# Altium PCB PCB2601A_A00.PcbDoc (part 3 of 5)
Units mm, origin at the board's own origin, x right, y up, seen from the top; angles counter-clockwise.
Board outline 30.4 x 51 mm, 8 copper layers (Top Layer, Signal Layer 2, Signal Layer 3, Signal Layer 4, Signal Layer 5, Signal Layer 6, Signal Layer 7, Bottom Layer), stack 1.492 mm thick; 194 components, 130 nets, 5039 pads, 478 vias.
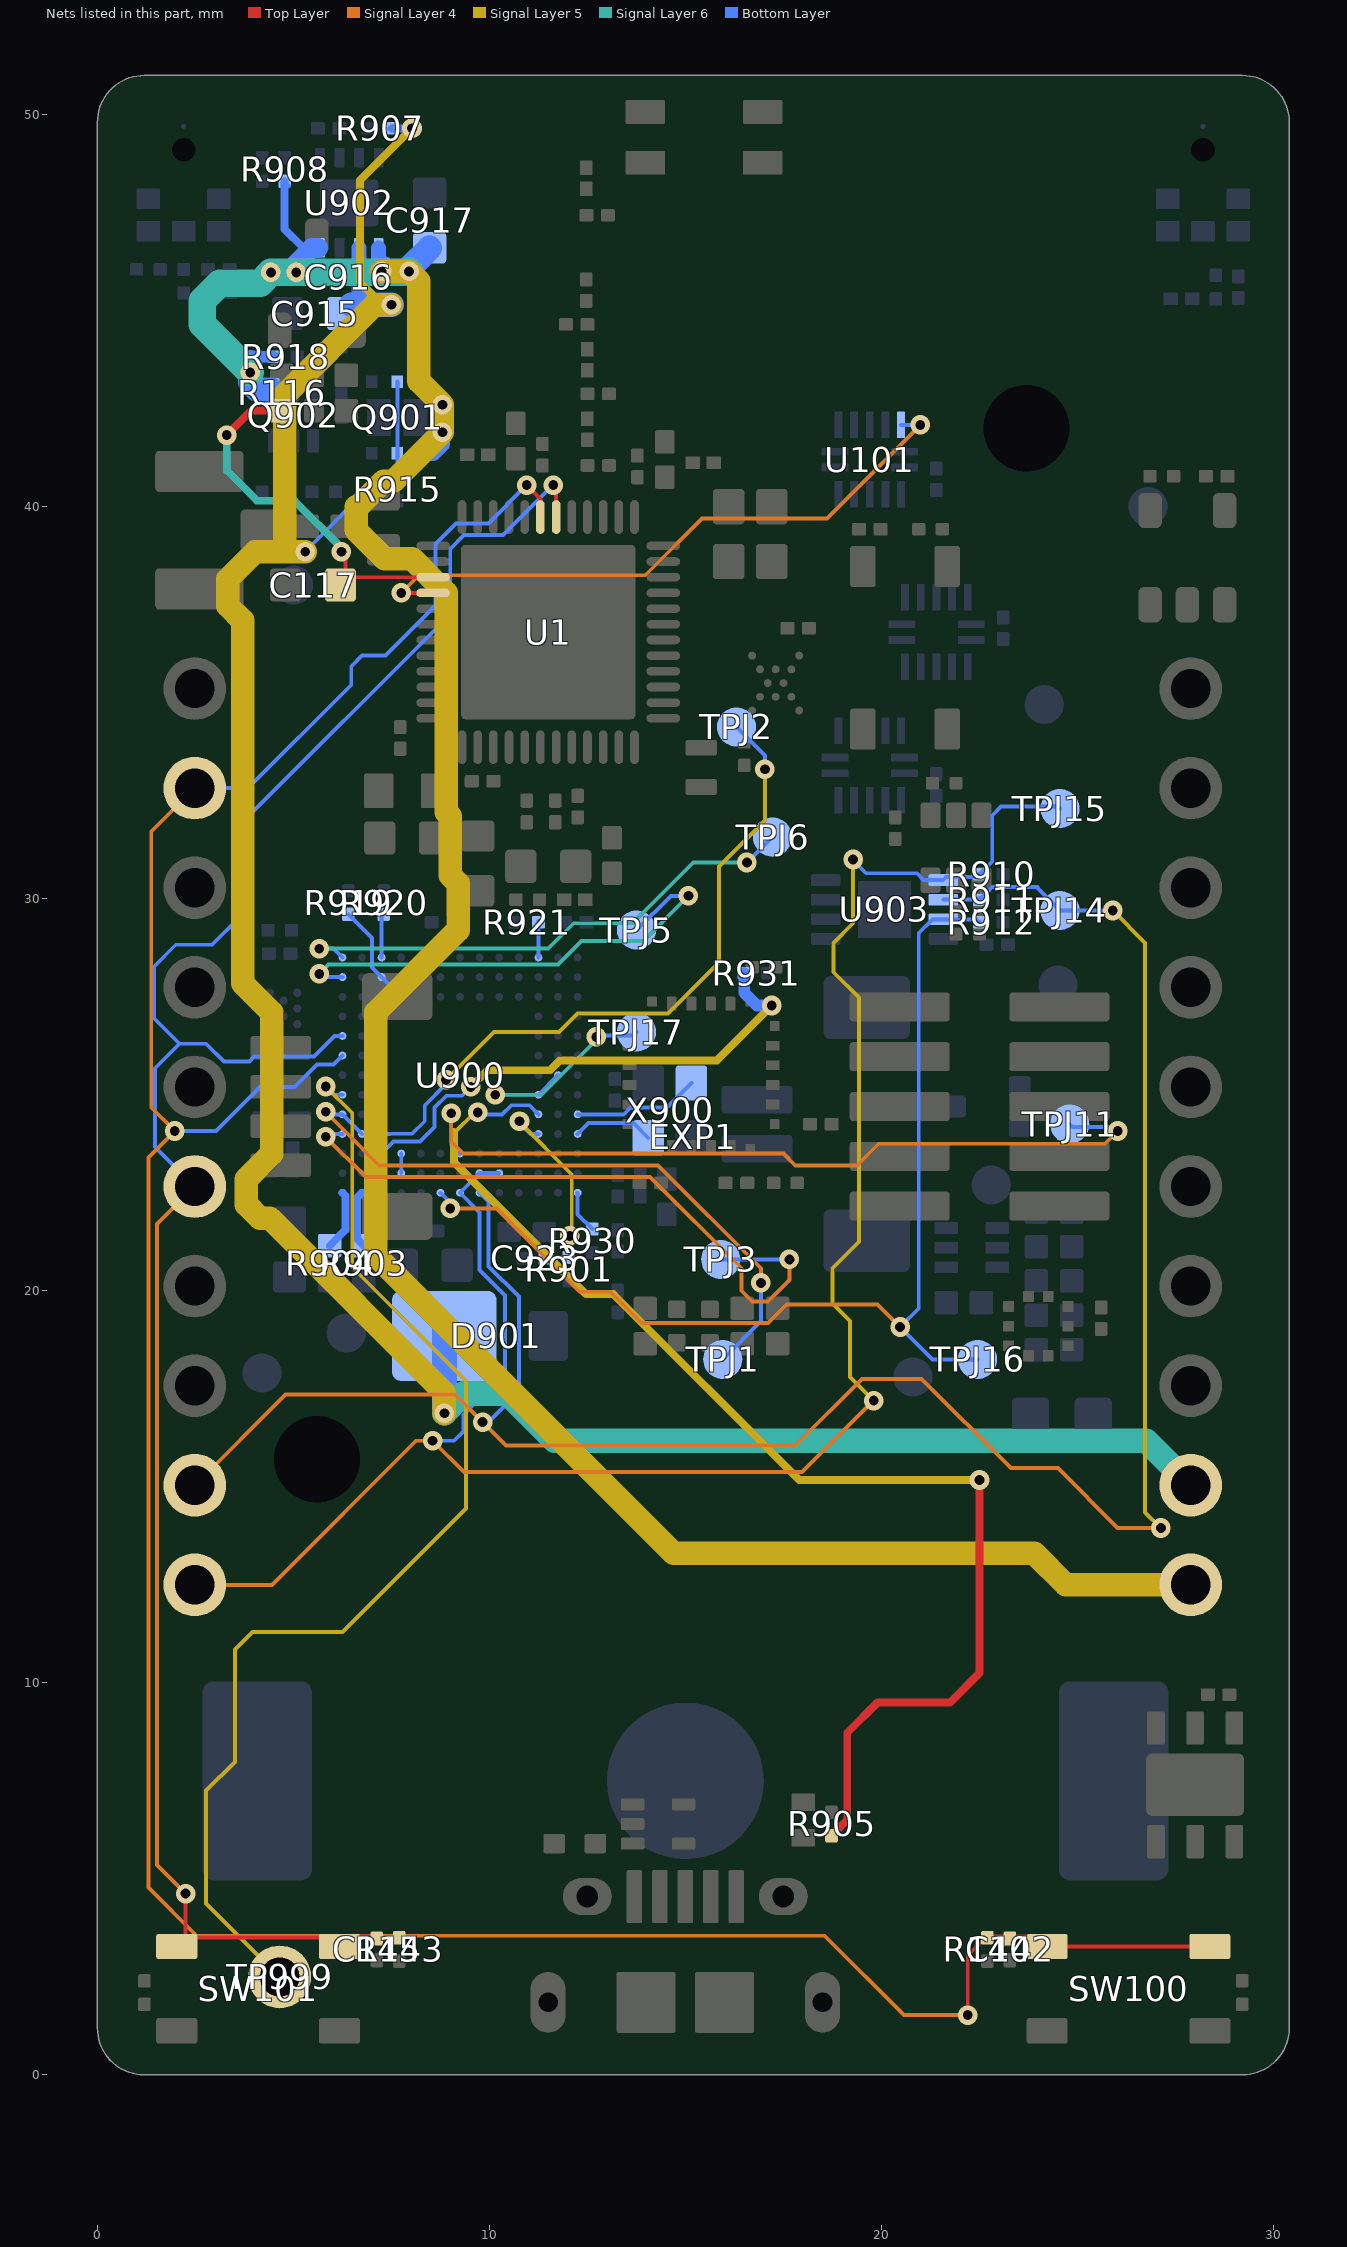
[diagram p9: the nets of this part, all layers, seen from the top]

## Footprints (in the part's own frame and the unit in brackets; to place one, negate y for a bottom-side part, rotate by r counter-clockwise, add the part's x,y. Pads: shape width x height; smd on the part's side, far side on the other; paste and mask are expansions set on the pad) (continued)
LOGO_SEGGER_8.0X4.0_SM [mil] "(210607)" (continued)
  round 0.8 on Mech2: 1(60.2,-56.26) 1(60.2,-56.26) 1(60.36,-56.74) 1(60.36,-56.74) 1(60.44,-56.9) 1(60.44,-56.9) 1(60.44,-56.82) 1(60.52,-29.06) 1(60.52,-29.06) 1(60.6,-57.14) 1(60.6,-57.14) 1(60.68,-57.3) 1(60.68,-57.3) 1(61.16,-36.58) 1(61.16,-36.58) 1(61.16,-29.46) 1(61.32,-57.94) 1(61.32,-57.94) 1(61.48,-29.7) 1(61.48,-29.7) 1(61.56,-58.02) 1(61.56,-58.02) 1(61.72,-58.1) 1(61.72,-58.1) 1(61.8,-36.42) 1(61.8,-36.42) 1(62.2,-58.26) 1(62.2,-58.26) 1(62.28,-40.98) 1(62.28,-40.98) 1(62.28,-36.1) 1(62.28,-36.1) 1(62.28,-30.5) 1(62.28,-30.5) 1(62.44,-58.26) 1(62.44,-58.26) 1(62.6,-35.94) 1(62.6,-35.94) 1(62.68,-58.34) 1(62.68,-58.34) 1(62.68,-35.86) 1(62.68,-30.82) 1(62.68,-30.82) 1(62.84,-41.06) 1(62.84,-41.06) 1(62.84,-31.06) 1(62.92,-58.34) 1(62.92,-58.34) 1(63.08,-35.46) 1(63.08,-35.46) 1(63.24,-58.26) 1(63.24,-58.26) 1(63.4,-34.98) 1(63.4,-34.98) 1(63.4,-32.02) 1(63.4,-32.02) 1(63.48,-34.74) 1(63.48,-34.74) 1(63.56,-58.26) 1(63.56,-58.26) 1(63.56,-32.34) 1(63.56,-32.34) 1(63.64,-41.22) 1(63.64,-41.22) 1(63.64,-34.42) 1(63.64,-34.42) 1(63.72,-34.26) 1(63.72,-34.18) 1(63.72,-34.18) 1(63.72,-32.74) 1(63.72,-32.74) 1(63.72,-32.66) 1(63.88,-58.18) 1(63.88,-58.18) 1(64.04,-41.38) 1(64.04,-41.38) 1(64.12,-58.18) 1(64.12,-58.18) 1(64.28,-41.46) 1(64.28,-41.46) 1(64.36,-58.02) 1(64.36,-58.02) 1(64.52,-57.94) 1(64.52,-57.94) 1(64.6,-41.62) 1(64.6,-41.62) 1(64.76,-57.78) 1(64.76,-57.78) 1(65,-42.02) 1(65,-42.02) 1(65.08,-57.46) 1(65.08,-57.46) 1(65.16,-57.3) 1(65.16,-57.3) 1(65.24,-42.34) 1(65.32,-57.06) 1(65.32,-57.06) 1(65.32,-42.5) 1(65.32,-42.5) 1(65.4,-56.82) 1(65.4,-56.74) 1(65.4,-56.74) 1(65.48,-56.5) 1(65.48,-56.5) 1(65.48,-56.18) 1(65.48,-56.18) 1(65.56,-55.94) 1(65.56,-55.94) 1(65.56,-55.14) 1(65.56,-53.54) 1(65.56,-51.94) 1(65.56,-50.34) 1(65.56,-48.74) 1(65.56,-47.14) 1(65.56,-45.54) 1(65.56,-43.94) 1(65.56,-43.46) 1(65.56,-43.46) 1(72.68,-54.02) 1(72.68,-54.02) 1(72.68,-52.66) 1(72.68,-51.06) 1(72.68,-49.46) 1(72.68,-47.86) 1(72.68,-46.26) 1(72.68,-44.66) 1(72.68,-43.06) 1(72.68,-41.46) 1(72.68,-39.86) 1(72.68,-38.18) 1(72.68,-36.58) 1(72.68,-34.98) 1(72.68,-33.38) 1(72.68,-31.78) 1(72.68,-30.5) 1(72.68,-30.5) 1(72.76,-54.58) 1(72.76,-54.58) 1(72.76,-54.26) 1(72.76,-30.18) 1(72.76,-29.94) 1(72.76,-29.94) 1(72.92,-55.3) 1(72.92,-55.3) 1(72.92,-55.06) 1(72.92,-55.06) 1(72.92,-29.38) 1(72.92,-29.38) 1(72.92,-29.14) 1(72.92,-29.14) 1(73,-55.54) 1(73,-55.54) 1(73,-28.98) 1(73,-28.98) 1(73.16,-55.78) 1(73.16,-55.78) 1(73.16,-28.74) 1(73.16,-28.74) 1(73.24,-55.94) 1(73.24,-28.58) 1(73.4,-56.26) 1(73.4,-56.26) 1(73.4,-28.26) 1(73.4,-28.26) 1(73.56,-56.42) 1(73.56,-56.42) 1(73.56,-28.1) 1(73.56,-28.1) 1(73.64,-56.58) 1(73.64,-56.58) 1(73.64,-27.94) 1(73.64,-27.94) 1(73.72,-56.66) 1(73.72,-56.66) 1(73.88,-56.74) 1(73.88,-56.74) 1(73.88,-27.7) 1(73.88,-27.7) 1(74.04,-56.9) 1(74.04,-56.9) 1(74.04,-27.62) 1(74.04,-27.62) 1(74.2,-27.46) 1(74.2,-27.46) 1(74.36,-57.06) 1(74.36,-57.06) 1(74.36,-27.46) 1(74.36,-27.46) 1(74.6,-57.14) 1(74.6,-57.14) 1(74.6,-27.3) 1(74.6,-27.3) 1(74.76,-57.22) 1(74.76,-57.22) 1(74.76,-27.22) 1(74.76,-27.22) 1(75,-57.3) 1(75,-57.3) 1(75,-27.22) 1(75,-27.22) 1(75.48,-27.06) 1(75.48,-27.06) 1(75.96,-57.46) 1(75.96,-57.46) 1(75.96,-26.98) 1(75.96,-26.98) 1(75.96,-26.98) 1(76.52,-57.54) 1(76.52,-57.54) 1(76.52,-26.98) 1(76.52,-26.98) 1(77.16,-26.9) 1(77.16,-26.9) 1(79.96,-51.94) 1(79.96,-51.94) 1(79.96,-51.06) 1(79.96,-49.46) 1(79.96,-47.86) 1(79.96,-46.26) 1(79.96,-44.66) 1(79.96,-44.02) 1(79.96,-44.02) 1(79.96,-38.74) 1(79.96,-38.74) 1(79.96,-38.18) 1(79.96,-36.58) 1(79.96,-34.98) 1(79.96,-33.38) 1(79.96,-32.26) 1(79.96,-32.26) 1(93.72,-38.74) 1(93.72,-38.74) 1(94.2,-44.02) 1(94.2,-44.02) 1(94.2,-38.82) 1(94.2,-38.82) 1(94.68,-43.94) 1(94.68,-43.94) 1(94.68,-38.82) 1(94.68,-38.82) 1(95.08,-43.94) 1(95.08,-43.94) 1(95.08,-38.9) 1(95.08,-38.9) 1(95.24,-26.9) 1(95.24,-26.9) 1(95.48,-43.86) 1(95.48,-43.86) 1(95.48,-38.9) 1(95.48,-38.9) 1(95.72,-32.26) 1(95.72,-32.26) 1(95.72,-26.98) 1(95.72,-26.98) 1(95.8,-43.78) 1(95.8,-43.78) 1(95.8,-39.06) 1(95.8,-39.06) 1(96.12,-43.62) 1(96.12,-43.62) 1(96.12,-39.14) 1(96.12,-39.14) 1(96.2,-32.18) 1(96.2,-32.18) 1(96.2,-26.98) 1(96.2,-26.98) 1(96.28,-26.98) 1(96.44,-43.54) 1(96.44,-43.54) 1(96.44,-39.3) 1(96.44,-39.3) 1(96.6,-32.18) 1(96.6,-32.18) 1(96.68,-51.94) 1(96.68,-51.94) 1(96.92,-43.22) 1(96.92,-43.22) 1(97.08,-43.06) 1(97.08,-42.98) 1(97.08,-42.98) 1(97.16,-57.54) 1(97.16,-57.54) 1(97.16,-52.02) 1(97.16,-52.02) 1(97.16,-39.78) 1(97.16,-39.78) 1(97.24,-39.86) 1(97.4,-32.02) 1(97.4,-32.02) 1(97.4,-27.22) 1(97.4,-27.22) 1(97.48,-42.58) 1(97.48,-42.58) 1(97.48,-40.26) 1(97.48,-40.26) 1(97.56,-52.02) 1(97.56,-52.02) 1(97.56,-42.26) 1(97.56,-42.26) 1(97.56,-40.5) 1(97.56,-40.5) 1(97.64,-42.02) 1(97.64,-42.02) 1(97.72,-41.7) 1(97.72,-41.7) 1(97.72,-41.46) 1(97.72,-41.14) 1(97.72,-41.14) 1(97.72,-31.86) 1(97.72,-31.86) 1(97.72,-27.3) 1(97.72,-27.3) 1(97.96,-31.78) 1(98.04,-31.78) 1(98.04,-31.78) 1(98.04,-27.46) 1(98.04,-27.46) 1(98.28,-31.62) 1(98.28,-31.62) 1(98.36,-57.3) 1(98.36,-57.3) 1(98.36,-52.18) 1(98.36,-52.18) 1(98.52,-31.38) 1(98.52,-31.38) 1(98.52,-27.78) 1(98.52,-27.78) 1(98.68,-57.14) 1(98.68,-57.14) 1(98.76,-31.22) 1(98.76,-31.22) 1(98.76,-28.02) 1(98.76,-28.02) 1(98.92,-56.98) 1(98.92,-56.98) 1(98.92,-30.98) 1(98.92,-30.98) 1(98.92,-28.26) 1(98.92,-28.26) 1(99,-52.5) 1(99,-52.5) 1(99,-30.74) 1(99,-30.74) 1(99,-28.5) 1(99,-28.5) 1(99.08,-28.58) 1(99.16,-30.5) 1(99.16,-30.5) 1(99.16,-28.74) 1(99.16,-28.74) 1(99.24,-56.82) 1(99.24,-56.82) 1(99.24,-30.26) 1(99.24,-30.26) 1(99.24,-28.98) 1(99.24,-28.98) 1(99.32,-52.66) 1(99.32,-30.18) 1(99.32,-29.94) 1(99.32,-29.94) 1(99.32,-29.3) 1(99.32,-29.3) 1(99.48,-56.66) 1(99.48,-56.66) 1(99.48,-52.82) 1(99.48,-52.82) 1(99.64,-56.42) 1(99.64,-56.42) 1(99.72,-53.06) 1(99.72,-53.06) 1(99.88,-56.18) 1(99.88,-56.18) 1(99.88,-53.3) 1(99.88,-53.3) 1(99.96,-55.94) 1(99.96,-55.94) 1(99.96,-55.94) 1(100.12,-55.7) 1(100.12,-55.7) 1(100.12,-53.78) 1(100.12,-53.78) 1(100.2,-55.38) 1(100.2,-55.38) 1(100.2,-55.06) 1(100.2,-55.06) 1(100.2,-54.42) 1(100.2,-54.42) 1(100.2,-54.26) 1(100.2,-54.1) 1(100.2,-54.1) 1(100.28,-54.74) 1(100.28,-54.74) 1(105.4,-54.98) 1(105.4,-54.98) 1(105.4,-54.66) 1(105.4,-53.06) 1(105.4,-51.46) 1(105.4,-49.86) 1(105.4,-48.26) 1(105.4,-46.66) 1(105.4,-45.06) 1(105.4,-43.46) 1(105.4,-41.86) 1(105.4,-40.26) 1(105.4,-38.58) 1(105.4,-36.98) 1(105.4,-35.38) 1(105.4,-33.78) 1(105.4,-32.18) 1(105.4,-31.06) 1(105.4,-31.06) 1(105.48,-55.38) 1(105.48,-55.38) 1(105.48,-30.58) 1(105.64,-56.02) 1(105.64,-56.02) 1(105.64,-29.38) 1(105.64,-29.38) 1(105.72,-29.14) 1(105.72,-29.14) 1(105.8,-56.34) 1(105.8,-56.34) 1(105.8,-56.34) 1(105.8,-28.98) 1(105.8,-28.98) 1(105.8,-28.98) 1(105.88,-28.74) 1(105.88,-28.74) 1(106.04,-28.42) 1(106.04,-28.42) 1(106.12,-56.82) 1(106.12,-56.82) 1(106.2,-28.26) 1(106.2,-28.26) 1(106.36,-27.94) 1(106.36,-27.94) 1(106.52,-27.86) 1(106.52,-27.86) 1(106.6,-57.3) 1(106.6,-57.3) 1(106.68,-27.7) 1(106.68,-27.7) 1(106.84,-57.46) 1(106.84,-57.46) 1(106.84,-27.62) 1(106.84,-27.62) 1(107,-27.46) 1(107,-27.46) 1(107.16,-57.62) 1(107.16,-57.62) 1(107.16,-27.46) 1(107.16,-27.46) 1(107.24,-27.38) 1(107.32,-27.3) 1(107.32,-27.3) 1(107.48,-57.7) 1(107.48,-57.7) 1(107.56,-27.22) 1(107.56,-27.22) 1(107.8,-27.22) 1(107.8,-27.22) 1(108.2,-27.06) 1(108.2,-27.06) 1(108.68,-57.94) 1(108.68,-57.94) 1(108.76,-26.98) 1(108.76,-26.98) 1(109.32,-26.98) 1(109.32,-26.98) 1(109.56,-57.94) 1(109.56,-57.94) 1(109.96,-26.9) 1(109.96,-26.9) 1(110.04,-57.86) 1(110.04,-57.86) 1(110.44,-57.78) 1(110.44,-57.78) 1(111.08,-57.62) 1(111.08,-57.62) 1(111.4,-57.46) 1(111.4,-57.46) 1(111.64,-57.3) 1(111.64,-57.3) 1(111.96,-57.06) 1(111.96,-57.06) 1(112.12,-56.9) 1(112.12,-56.9) 1(112.36,-56.58) 1(112.36,-56.58) 1(112.44,-56.34) 1(112.44,-56.34) 1(112.44,-56.34) 1(112.6,-56.02) 1(112.6,-56.02) 1(112.76,-55.38) 1(112.76,-55.38) 1(112.84,-54.98) 1(112.84,-54.98) 1(112.84,-54.66) 1(112.84,-53.06) 1(112.84,-51.46) 1(112.84,-49.86) 1(112.84,-48.26) 1(112.84,-46.66) 1(112.84,-45.62) 1(112.84,-45.62) 1(112.84,-40.34) 1(112.84,-40.34) 1(112.84,-40.26) 1(112.84,-38.58) 1(112.84,-36.98) 1(112.84,-35.38) 1(112.84,-33.78) 1(112.84,-32.18) 1(112.84,-32.18) 1(112.84,-32.18) 1(120.68,-45.62) 1(120.68,-45.62) 1(121.4,-45.7) 1(121.4,-45.7) 1(121.88,-32.18) 1(121.88,-32.18) 1(122.04,-45.7) 1(122.04,-45.7) 1(122.2,-32.18) 1(122.28,-40.34) 1(122.28,-40.34) 1(122.52,-32.26) 1(122.52,-32.26) 1(122.92,-40.26) 1(122.92,-40.26) 1(122.92,-26.9) 1(122.92,-26.9) 1(123,-40.26) 1(123.16,-45.86) 1(123.16,-45.86) 1(123.16,-32.26) 1(123.16,-32.26) 1(123.56,-45.94) 1(123.56,-45.94) 1(123.64,-32.34) 1(123.64,-32.34) 1(123.64,-26.98) 1(123.64,-26.98) 1(124.04,-46.1) 1(124.04,-46.1) 1(124.04,-40.1) 1(124.04,-40.1) 1(124.2,-46.18) 1(124.2,-46.18) 1(124.2,-32.5) 1(124.2,-32.5) 1(124.36,-46.34) 1(124.36,-46.34) 1(124.36,-26.98) 1(124.36,-26.98) 1(124.6,-32.58) 1(124.6,-32.58) 1(124.68,-46.5) 1(124.68,-46.5) 1(124.92,-46.66) 1(125,-39.78) 1(125,-39.78) 1(125,-32.82) 1(125,-32.82) 1(125,-27.06) 1(125,-27.06) 1(125.08,-46.9) 1(125.08,-46.9) 1(125.16,-47.14) 1(125.16,-47.14) 1(125.16,-39.7) 1(125.16,-39.7) 1(125.24,-32.9) 1(125.24,-32.9) 1(125.32,-47.3) 1(125.32,-47.3) 1(125.4,-39.54) 1(125.4,-39.54) 1(125.4,-32.98) 1(125.4,-32.98) 1(125.48,-47.78) 1(125.48,-47.78) 1(125.56,-48.1) 1(125.56,-48.1) 1(125.64,-48.26) 1(125.64,-33.14) 1(125.64,-33.14) 1(125.64,-27.06) 1(125.64,-27.06) 1(125.72,-48.66) 1(125.72,-48.66) 1(125.72,-39.38) 1(125.72,-39.38) 1(125.8,-33.22) 1(125.8,-33.22) 1(125.88,-49.38) 1(125.88,-49.38) 1(125.96,-33.38) 1(125.96,-33.38) 1(126.04,-51.06) 1(126.04,-51.06) 1(126.04,-50.18) 1(126.04,-50.18) 1(126.04,-49.86) 1(126.04,-33.54) 1(126.04,-33.54) 1(126.12,-51.46) 1(126.2,-52.18) 1(126.2,-52.18) 1(126.2,-33.62) 1(126.2,-33.62) 1(126.28,-53.14) 1(126.28,-53.14) 1(126.28,-53.06) 1(126.36,-33.78) 1(126.36,-33.78) 1(126.44,-54.02) 1(126.44,-54.02) 1(126.44,-38.66) 1(126.44,-38.66) 1(126.44,-38.58) 1(126.44,-34.02) 1(126.44,-34.02) 1(126.44,-33.78) 1(126.6,-54.82) 1(126.6,-54.82) 1(126.6,-54.66) 1(126.6,-38.42) 1(126.6,-38.42) 1(126.6,-34.18) 1(126.6,-34.18) 1(126.76,-34.5) 1(126.76,-34.5) 1(126.84,-55.78) 1(126.84,-55.78) 1(126.84,-37.94) 1(126.84,-37.94) 1(126.84,-34.74) 1(126.84,-34.74) 1(126.92,-37.7) 1(126.92,-37.7) 1(126.92,-37.46) 1(126.92,-37.46) 1(126.92,-34.9) 1(126.92,-34.9) 1(126.92,-27.22) 1(126.92,-27.22) 1(127,-56.02) 1(127,-56.02) 1(127,-37.22) 1(127,-37.22) 1(127,-35.3) 1(127,-35.3) 1(127,-35.14) 1(127,-35.14) 1(127.08,-56.26) 1(127.08,-56.26) 1(127.08,-36.98) 1(127.08,-36.74) 1(127.08,-36.74) 1(127.08,-35.78) 1(127.08,-35.78) 1(127.08,-35.38) 1(127.16,-56.34) 1(127.24,-56.5) 1(127.24,-56.5) 1(127.32,-56.66) 1(127.32,-56.66) 1(127.48,-56.82) 1(127.48,-56.82) 1(127.48,-27.38) 1(127.48,-27.38) 1(127.56,-56.98) 1(127.56,-56.98) 1(127.56,-27.38) 1(127.72,-57.06) 1(127.72,-57.06) 1(127.88,-57.22) 1(127.88,-57.22) 1(128.04,-57.3) 1(128.04,-57.3) 1(128.04,-27.46) 1(128.04,-27.46) 1(128.2,-57.46) 1(128.2,-57.46) 1(128.36,-57.54) 1(128.36,-57.54) 1(128.6,-57.62) 1(128.6,-57.62) 1(128.6,-27.62) 1(128.6,-27.62) 1(128.76,-57.7) 1(128.76,-57.7) 1(129.16,-42.82) 1(129.16,-42.82) 1(129.56,-27.94) 1(129.56,-27.94) 1(129.64,-43.06) 1(129.64,-43.06) 1(130.04,-28.18) 1(130.04,-28.18) 1(130.12,-43.22) 1(130.12,-43.22) 1(130.12,-42.58) 1(130.12,-42.58) 1(130.2,-57.94) 1(130.2,-57.94) 1(130.36,-42.42) 1(130.36,-42.42) 1(130.52,-43.38) 1(130.52,-43.38) 1(130.52,-28.34) 1(130.52,-28.34) 1(130.68,-43.46) 1(130.68,-42.34) 1(130.68,-42.34) 1(131.32,-43.86) 1(131.32,-43.86) 1(131.32,-28.82) 1(131.32,-28.82) 1(131.4,-41.86) 1(131.4,-41.86) 1(131.4,-41.86) 1(131.56,-57.94) 1(131.56,-57.94) 1(131.56,-28.98) 1(131.64,-44.1) 1(131.64,-44.1) 1(131.64,-29.06) 1(131.64,-29.06) 1(131.72,-41.7) 1(131.72,-41.7) 1(131.96,-57.86) 1(131.96,-57.86) 1(131.96,-41.54) 1(131.96,-41.54) 1(132.04,-29.38) 1(132.04,-29.38) 1(132.28,-57.78) 1(132.28,-57.78) 1(132.36,-41.14) 1(132.36,-41.14) 1(132.36,-29.62) 1(132.36,-29.62) 1(132.52,-44.98) 1(132.52,-44.98) 1(132.6,-57.62) 1(132.6,-57.62) 1(132.6,-45.06) 1(132.6,-40.98) 1(132.6,-40.98) 1(132.6,-29.94) 1(132.6,-29.94) 1(132.68,-45.38) 1(132.68,-45.38) 1(132.92,-57.54) 1(132.92,-57.54) 1(132.92,-45.7) 1(132.92,-45.7) 1(132.92,-40.5) 1(132.92,-40.5) 1(132.92,-30.34) 1(132.92,-30.34) 1(133.08,-46.1) 1(133.08,-46.1) 1(133.16,-57.38) 1(133.16,-57.38) 1(133.16,-40.34) 1(133.16,-40.34) 1(133.16,-30.58) 1(133.24,-46.58) 1(133.24,-46.58) 1(133.24,-40.26) 1(133.32,-46.66) 1(133.32,-40.1) 1(133.32,-40.1) 1(133.4,-30.98) 1(133.4,-30.98) 1(133.48,-57.22) 1(133.48,-57.22) 1(133.48,-39.78) 1(133.48,-39.78) 1(133.56,-48.26) 1(133.64,-50.82) 1(133.64,-50.82) 1(133.64,-49.86) 1(133.64,-48.98) 1(133.64,-48.98) 1(133.64,-39.54) 1(133.64,-39.54) 1(133.64,-31.38) 1(133.64,-31.38) 1(133.72,-56.98) 1(133.72,-56.98) 1(133.72,-51.38) 1(133.72,-51.38) 1(133.72,-39.3) 1(133.72,-39.3) 1(133.8,-52.1) 1(133.8,-52.1) 1(133.8,-51.78) 1(133.8,-51.78) 1(133.8,-51.46) 1(133.88,-56.74) 1(133.88,-56.74) 1(133.88,-39.06) 1(133.88,-39.06) 1(133.96,-52.74) 1(133.96,-52.74) 1(133.96,-38.74) 1(133.96,-38.74) 1(133.96,-32.18) 1(133.96,-32.18) 1(133.96,-32.18) 1(134.04,-56.58) 1(134.04,-56.58) 1(134.04,-53.22) 1(134.04,-53.22) 1(134.04,-53.06) 1(134.04,-38.58) 1(134.04,-38.5) 1(134.04,-38.5) 1(134.12,-32.66) 1(134.12,-32.66) 1(134.2,-56.34) 1(134.2,-56.26) 1(134.2,-56.26) 1(134.2,-53.7) 1(134.2,-53.7) 1(134.2,-38.18) 1(134.2,-38.18) 1(134.2,-37.94) 1(134.2,-37.94) 1(134.2,-33.06) 1(134.2,-33.06) 1(134.28,-54.18) 1(134.28,-54.18) 1(134.36,-56.02) 1(134.36,-56.02) 1(134.36,-33.54) 1(134.36,-33.54) 1(134.44,-55.78) 1(134.44,-55.78) 1(134.44,-54.66) 1(134.44,-54.58) 1(134.44,-54.58) 1(134.44,-36.98) 1(134.44,-36.98) 1(134.44,-36.98) 1(134.44,-34.58) 1(134.44,-34.58) 1(134.44,-34.02) 1(134.44,-34.02) 1(134.44,-33.78) 1(134.52,-36.34) 1(134.52,-36.34) 1(134.52,-35.38) 1(134.52,-35.06) 1(134.52,-35.06) 1(135.4,-5.14) 1(135.4,-5.14) 1(135.4,14.54) 1(135.4,14.54) 1(135.8,-14.34) 1(135.8,-14.34) 1(135.8,-5.22) 1(135.8,-5.22) 1(135.8,5.34) 1(135.8,5.34) 1(135.8,14.46) 1(135.8,14.46) 1(136.2,-5.22) 1(136.2,-5.22) 1(136.2,14.46) 1(136.2,14.46) 1(137,-14.1) 1(137,-14.1) 1(137,-5.38) 1(137,-5.38) 1(137,5.58) 1(137,5.58) 1(137,14.3) 1(137,14.3) 1(137.16,-14.02) 1(137.64,-13.78) 1(137.64,-13.78) 1(137.64,-5.7) 1(137.64,-5.7) 1(137.64,13.98) 1(137.64,13.98) 1(137.8,-13.62) 1(137.8,-13.62) 1(137.8,-5.86) 1(137.8,-5.86) 1(137.8,5.98) 1(137.8,5.98) 1(137.96,-13.54) 1(137.96,-13.54) 1(137.96,-5.94) 1(137.96,-5.94) 1(137.96,13.66) 1(137.96,13.66) 1(138.04,-5.94) 1(138.12,13.58) 1(138.12,13.58) 1(138.28,-13.22) 1(138.28,-13.22) 1(138.28,-6.26) 1(138.28,-6.26) 1(138.28,6.46) 1(138.28,6.46) 1(138.28,13.42) 1(138.28,13.42) 1(138.36,-13.06) 1(138.36,-13.06) 1(138.36,-6.42) 1(138.36,-6.42) 1(138.36,6.62) 1(138.36,6.62) 1(138.36,13.18) 1(138.36,13.18) 1(138.36,13.42) 1(138.52,-12.82) 1(138.52,-12.82) 1(138.52,-6.66) 1(138.52,-6.66) 1(138.52,6.78) 1(138.52,6.78) 1(138.52,13.02) 1(138.52,13.02) 1(138.6,-12.66) 1(138.6,-12.66) 1(138.6,6.94) 1(138.68,-12.42) 1(138.76,-12.18) 1(138.76,-12.18) 1(138.76,-7.38) 1(138.76,-7.38) 1(138.76,7.5) 1(138.76,7.5) 1(138.76,12.3) 1(138.76,12.3) 1(138.92,-11.86) 1(138.92,-11.86) 1(138.92,-11.62) 1(138.92,-11.62) 1(138.92,-7.94) 1(138.92,-7.94) 1(138.92,-7.62) 1(138.92,-7.62) 1(138.92,-7.62) 1(138.92,7.82) 1(138.92,7.82) 1(138.92,8.06) 1(138.92,8.06) 1(138.92,11.74) 1(138.92,11.74) 1(138.92,11.82) 1(138.92,12.06) 1(138.92,12.06) 1(139,-11.3) 1(139,-11.3) 1(139,8.38) 1(139,8.38) 1(139.08,-10.9) 1(139.08,-10.9) 1(139.08,-10.82) 1(139.08,-9.22) 1(139.08,-8.58) 1(139.08,-8.58) 1(139.08,8.62) 1(139.08,8.78) 1(139.08,8.78) 1(139.08,10.22) 1(139.08,11.1) 1(139.08,11.1) 1(145,78.78) 1(145,78.78) 1(145.32,72.22) 1(145.32,72.22) 1(145.56,-72.02) 1(145.56,-72.02) 1(145.56,72.14) 1(145.56,72.14) 1(145.64,-78.58) 1(145.64,-78.58) 1(145.64,78.7) 1(145.64,78.7) 1(145.88,-71.94) 1(145.88,-71.94) 1(145.88,72.14) 1(145.88,72.14) 1(146.12,-71.94) 1(146.12,-71.94) 1(146.12,72.06) 1(146.12,72.06) 1(146.28,78.7) 1(146.28,78.7) 1(146.44,-71.86) 1(146.44,-71.86) 1(146.44,71.98) 1(146.44,71.98) 1(146.68,-71.78) 1(146.68,-71.78) 1(146.68,71.9) 1(146.68,71.9) 1(146.92,78.62) 1(146.92,78.62) 1(147,-71.62) 1(147,-71.62) 1(147,71.82) 1(147,71.82) 1(147.24,-71.54) 1(147.24,-71.54) 1(147.24,71.74) 1(147.24,71.74) 1(147.48,-71.38) 1(147.48,-71.38) 1(147.56,-78.34) 1(147.56,-78.34) 1(147.56,78.46) 1(147.56,78.46) 1(147.72,-71.3) 1(147.72,-71.3) 1(147.72,71.42) 1(147.72,71.42) 1(147.96,71.34) 1(147.96,71.34) 1(148.12,-78.18) 1(148.12,-78.18) 1(148.12,78.3) 1(148.12,78.3) 1(148.2,71.18) 1(148.2,71.18) 1(148.44,-70.82) 1(148.44,-70.82) 1(148.44,70.94) 1(148.44,70.94) 1(148.44,71.02) 1(148.68,70.78) 1(148.68,70.78) 1(148.76,-78.02) 1(148.76,-78.02) 1(148.76,-70.5) 1(148.76,78.14) 1(148.76,78.14) 1(149.32,-69.94) 1(149.32,-69.94) 1(149.32,70.14) 1(149.32,70.14) 1(149.32,77.98) 1(149.32,77.98) 1(149.48,-69.7) 1(149.48,-69.7) 1(149.48,69.9) 1(149.48,69.9) 1(149.72,-69.46) 1(149.72,-69.46) 1(149.72,69.66) 1(149.72,69.66) 1(149.88,69.42) 1(149.88,69.42) 1(149.88,77.74) 1(149.88,77.74) 1(149.96,69.42) 1(150.04,-68.98) 1(150.04,-68.98) 1(150.04,69.1) 1(150.04,69.1) 1(150.12,-68.9) 1(150.2,-68.66) 1(150.2,-68.66) 1(150.2,68.86) 1(150.2,68.86) 1(150.28,-68.42) 1(150.28,-68.42) 1(150.28,68.54) 1(150.28,68.54) 1(150.44,-77.3) 1(150.44,-77.3) 1(150.44,-68.1) 1(150.44,-68.1) 1(150.44,68.3) 1(150.44,68.3) 1(150.44,77.42) 1(150.44,77.42) 1(150.52,77.42) 1(150.6,-67.46) 1(150.6,-67.46) 1(150.6,67.74) 1(150.68,-67.3) 1(150.68,-67.22) 1(150.68,-67.22) 1(150.76,-66.82) 1(150.76,-66.82) 1(150.84,-66.5) 1(150.84,-66.5) 1(150.84,-66.18) 1(150.84,-66.18) 1(150.84,66.38) 1(150.84,66.38) 1(150.84,66.7) 1(150.84,66.7) 1(150.92,-65.86) 1(150.92,-65.86) 1(150.92,-65.7) 1(150.92,-64.1) 1(150.92,-62.5) 1(150.92,-60.9) 1(150.92,-59.22) 1(150.92,-57.62) 1(150.92,-56.02) 1(150.92,-54.42) 1(150.92,-52.82) 1(150.92,-51.22) 1(150.92,-49.62) 1(150.92,-48.02) 1(150.92,-46.42) 1(150.92,-44.82) 1(150.92,-43.14) 1(150.92,-41.54) 1(150.92,-39.94) 1(150.92,-38.34) 1(150.92,-36.74) 1(150.92,-35.14) 1(150.92,-33.54) 1(150.92,-31.94) 1(150.92,-30.34) 1(150.92,-28.74) 1(150.92,-27.06) 1(150.92,-25.46) 1(150.92,-23.86) 1(150.92,-22.26) 1(150.92,-20.66) 1(150.92,-19.06) 1(150.92,-17.46) 1(150.92,-15.86) 1(150.92,-14.26) 1(150.92,-12.66) 1(150.92,-10.98) 1(150.92,-9.38) 1(150.92,-7.78) 1(150.92,-6.18) 1(150.92,-4.58) 1(150.92,-2.98) 1(150.92,-1.38) 1(150.92,0.22) 1(150.92,1.82) 1(150.92,3.42) 1(150.92,5.1) 1(150.92,6.7) 1(150.92,8.3) 1(150.92,9.9) 1(150.92,11.5) 1(150.92,13.1) 1(150.92,14.7) 1(150.92,16.3) 1(150.92,17.9) 1(150.92,19.5) 1(150.92,21.18) 1(150.92,22.78) 1(150.92,24.38) 1(150.92,25.98) 1(150.92,27.58) 1(150.92,29.18) 1(150.92,30.78) 1(150.92,32.38) 1(150.92,33.98) 1(150.92,35.58) 1(150.92,37.26) 1(150.92,38.86) 1(150.92,40.46) 1(150.92,42.06) 1(150.92,43.66) 1(150.92,45.26) 1(150.92,46.86) 1(150.92,48.46) 1(150.92,50.06) 1(150.92,51.66) 1(150.92,53.34) 1(150.92,54.94) 1(150.92,56.54) 1(150.92,58.14) 1(150.92,59.74) 1(150.92,61.34) 1(150.92,62.94) 1(150.92,64.54) 1(150.92,66.06) 1(150.92,66.06) 1(150.92,66.14) 1(151,-76.98) 1(151,-76.98) 1(151,77.18) 1(151,77.18) 1(151.08,-76.98) 1(151.48,-76.66) 1(151.48,-76.66) 1(151.48,76.86) 1(151.48,76.86) 1(152.04,-76.34) 1(152.04,-76.34) 1(152.04,76.46) 1(152.04,76.46) 1(152.52,76.06) 1(152.52,76.06) 1(152.92,75.82) 1(153,75.74) 1(153,75.74) 1(153.24,-75.3) 1(153.48,-75.14) 1(153.48,-75.14) 1(153.88,74.86) 1(153.88,74.86) 1(154.28,-74.18) 1(154.28,-74.18) 1(154.44,74.22) 1(154.68,-73.78) 1(154.68,-73.78) 1(154.68,73.9) 1(154.68,73.9) 1(154.76,-73.7) 1(155,-73.22) 1(155,-73.22) 1(155.32,-72.74) 1(155.32,-72.74) 1(155.32,72.94) 1(155.32,72.94) 1(155.64,72.62) 1(155.72,-72.18) 1(155.72,-72.18) 1(155.72,72.38) 1(155.72,72.38) 1(155.8,-72.1) 1(155.96,-71.7) 1(155.96,-71.7) 1(155.96,71.82) 1(155.96,71.82) 1(156.28,-71.14) 1(156.28,-71.14) 1(156.28,71.26) 1(156.28,71.26) 1(156.44,71.02) 1(156.52,-70.5) 1(156.52,-70.5) 1(156.52,-70.5) 1(156.76,-69.94) 1(156.76,-69.94) 1(156.76,70.14) 1(156.76,70.14) 1(156.92,-69.38) 1(156.92,-69.38) 1(156.92,69.5) 1(156.92,69.5) 1(157,69.42) 1(157.08,-68.9) 1(157.08,68.94) 1(157.08,68.94) 1(157.24,-68.1) 1(157.24,-68.1) 1(157.24,68.3) 1(157.24,68.3) 1(157.32,67.74) 1(157.4,-67.3) 1(157.4,-66.82) 1(157.4,-66.82) 1(157.4,-66.18) 1(157.4,-66.18) 1(157.4,66.38) 1(157.4,66.38) 1(157.4,67.02) 1(157.4,67.02) 1(157.48,-65.7) 1(157.48,-65.54) 1(157.48,-65.54) 1(157.48,-64.1) 1(157.48,-62.5) 1(157.48,-60.9) 1(157.48,-59.22) 1(157.48,-57.62) 1(157.48,-56.02) 1(157.48,-54.42) 1(157.48,-52.82) 1(157.48,-51.22) 1(157.48,-49.62) 1(157.48,-48.02) 1(157.48,-46.42) 1(157.48,-44.82) 1(157.48,-43.14) 1(157.48,-41.54) 1(157.48,-39.94) 1(157.48,-38.34) 1(157.48,-36.74) 1(157.48,-35.14) 1(157.48,-33.54) 1(157.48,-31.94) 1(157.48,-30.34) 1(157.48,-28.74) 1(157.48,-27.06) 1(157.48,-25.46) 1(157.48,-23.86) 1(157.48,-22.26) 1(157.48,-20.66) 1(157.48,-19.06) 1(157.48,-17.46) 1(157.48,-15.86) 1(157.48,-14.26) 1(157.48,-12.66) 1(157.48,-10.98) 1(157.48,-9.38) 1(157.48,-7.78) 1(157.48,-6.18) 1(157.48,-4.58) 1(157.48,-2.98) 1(157.48,-1.38) 1(157.48,0.22) 1(157.48,1.82) 1(157.48,3.42) 1(157.48,5.1) 1(157.48,6.7) 1(157.48,8.3) 1(157.48,9.9) 1(157.48,11.5) 1(157.48,13.1) 1(157.48,14.7) 1(157.48,16.3) 1(157.48,17.9) 1(157.48,19.5) 1(157.48,21.18) 1(157.48,22.78) 1(157.48,24.38) 1(157.48,25.98) 1(157.48,27.58) 1(157.48,29.18) 1(157.48,30.78) 1(157.48,32.38) 1(157.48,33.98) 1(157.48,35.58) 1(157.48,37.26) 1(157.48,38.86) 1(157.48,40.46) 1(157.48,42.06) 1(157.48,43.66) 1(157.48,45.26) 1(157.48,46.86) 1(157.48,48.46) 1(157.48,50.06) 1(157.48,51.66) 1(157.48,53.34) 1(157.48,54.94) 1(157.48,56.54) 1(157.48,58.14) 1(157.48,59.74) 1(157.48,61.34) 1(157.48,62.94) 1(157.48,64.54) 1(157.48,65.66) 1(157.48,65.66) 1(157.48,66.14)
  round 0.79 on Mech2: 1(-15.75,0) 1(0,-15.75) 1(0,15.75) 1(15.75,0)
  silkscreen extent -157,-79 157,79
LOGO_SILABS_W14.0 [mm] "LOGO_SILABS_W14.0"
  silkscreen extent 0.03,0 13.99,6.83
MIC_INVENSENSE_ICS-43434 [mm] "(210603)"
  rrect10% 0.6x0.522 smd mask+0.05: 1(0.9,-2.074) 2(0.9,-1.252) 4(-0.9,-1.252) 5(-0.9,-2.074) 6(0,-2.074)
  round 0.127 smd paste-100 mask-100: 3(0,0.6)
  round 0 hole 0.6 unplated mask+0.1: H1(0,0)
  Top Layer pour cut-out: 0,-1 -0.383,-0.924 -0.707,-0.707 -0.924,-0.383 -1,0 -1,0 -0.924,0.383 -0.707,0.707 -0.383,0.924 0,1 0,1 0.383,0.924 0.707,0.707 0.924,0.383 1,0 1,0 0.924,-0.383 0.707,-0.707 0.383,-0.924 0,-1
  Top Layer lines w0.3: 0.662,0 ccw(c0,0) 0,0.662 ccw(c0,0) -0.662,0 ccw(c0,0) 0.662,0
  silkscreen extent -1.33,-2.46 1.33,1.04, body extent -1.33,-2.45 1.33,1.05, height 1.01
POWERPAK_SC70-6_L [mm] "POWERPAK SC70-6 Hich Dencity (Class C) (Vishay)"
  rrect10% 0.325x0.3 smd paste-0.025 mask+0.07: 1(-0.913,0.65) 2(-0.913,0) 3(-0.913,-0.65) 4(0.913,-0.65) 5(0.913,0) 6(0.913,0.65)
  rrect10% 0.95x0.613 smd paste-0.025 mask+0.07: 7(0,0.466) 8(0,-0.466)
  silkscreen extent -1.03,-1.02 1.02,1.05, body extent -1.02,-1.02 1.02,1.05, height 0.8
PROTO_TH [mm] "Test Point, 1.0 mm (= TP_1.0_D62)"
  round 1.6 hole 1: 1(0,0)
  silkscreen extent -0.84,-0.84 0.84,0.84
QFN14_M040_2.0X2.0_TI_RUC [mm] "QFN 14 Leads, Pitch 0.4 mm, 2.0 x 2.0 H: 0.37, TI: RUC (170308)"
  rrect20% 0.68x0.2 smd paste+0 mask+0.05: 1(-0.885,0.8) 2(-0.885,0.4) 3(-0.885,0) 4(-0.885,-0.4) 5(-0.885,-0.8) 8(0.885,-0.8) 9(0.885,-0.4) 10(0.885,0) 11(0.885,0.4) 12(0.885,0.8)
  rrect20% 0.2x0.68 smd paste+0 mask+0.05: 6(-0.2,-0.885) 7(0.2,-0.885) 13(0.2,0.885) 14(-0.2,0.885)
  silkscreen extent -1,-1 1,1, body extent -1,-1 1,1, height 0.41
QFN24_M050_4.0X4.0_NO_EP_ICM-20689 [mm] "QFN24, Pitch 0.50 4.0x4.0 H0.8 (210611)"
  rrect20% 0.25x0.25 smd: 1(-1.875,1.25) 6(-1.875,-1.25) 7(-1.25,-1.875) 12(1.25,-1.875) 13(1.875,-1.25) 18(1.875,1.25) 19(1.25,1.875) 24(-1.25,1.875)
  rrect20% 0.35x0.25 smd: 2(-1.825,0.75) 3(-1.825,0.25) 4(-1.825,-0.25) 5(-1.825,-0.75) 14(1.825,-0.75) 15(1.825,-0.25) 16(1.825,0.25) 17(1.825,0.75)
  rrect20% 0.25x0.35 smd: 8(-0.75,-1.825) 9(-0.25,-1.825) 10(0.25,-1.825) 11(0.75,-1.825) 20(0.75,1.825) 21(0.25,1.825) 22(-0.25,1.825) 23(-0.75,1.825)
  Top Layer region: -1.9,-1.125 -1.9,-1.375 -1.76,-1.375 -1.751,-1.373 -1.743,-1.368 -1.743,-1.368 -1.657,-1.282 -1.652,-1.274 -1.65,-1.265 -1.65,-1.265 -1.65,-1.15 -1.653,-1.137 -1.663,-1.128 -1.675,-1.125 -1.675,-1.125
  Top Layer region: -1.125,-1.9 -1.375,-1.9 -1.375,-1.76 -1.373,-1.751 -1.368,-1.743 -1.368,-1.743 -1.282,-1.657 -1.274,-1.652 -1.265,-1.65 -1.265,-1.65 -1.15,-1.65 -1.137,-1.653 -1.128,-1.663 -1.125,-1.675 -1.125,-1.675
  Top Layer region: 1.125,-1.9 1.375,-1.9 1.375,-1.76 1.373,-1.751 1.368,-1.743 1.368,-1.743 1.282,-1.657 1.274,-1.652 1.265,-1.65 1.265,-1.65 1.15,-1.65 1.137,-1.653 1.128,-1.663 1.125,-1.675 1.125,-1.675
  Top Layer region: 1.9,-1.125 1.9,-1.375 1.76,-1.375 1.751,-1.373 1.743,-1.368 1.743,-1.368 1.657,-1.282 1.652,-1.274 1.65,-1.265 1.65,-1.265 1.65,-1.15 1.653,-1.137 1.663,-1.128 1.675,-1.125 1.675,-1.125
  Top Layer region: 1.9,1.125 1.9,1.375 1.76,1.375 1.751,1.373 1.743,1.368 1.743,1.368 1.657,1.282 1.652,1.274 1.65,1.265 1.65,1.265 1.65,1.15 1.653,1.137 1.663,1.128 1.675,1.125 1.675,1.125
  Top Layer region: 1.125,1.9 1.375,1.9 1.375,1.76 1.373,1.751 1.368,1.743 1.368,1.743 1.282,1.657 1.274,1.652 1.265,1.65 1.265,1.65 1.15,1.65 1.137,1.653 1.128,1.663 1.125,1.675 1.125,1.675
  Top Layer region: -1.125,1.9 -1.375,1.9 -1.375,1.76 -1.373,1.751 -1.368,1.743 -1.368,1.743 -1.282,1.657 -1.274,1.652 -1.265,1.65 -1.265,1.65 -1.15,1.65 -1.137,1.653 -1.128,1.663 -1.125,1.675 -1.125,1.675
  Top Layer region: -1.9,1.125 -1.9,1.375 -1.76,1.375 -1.751,1.373 -1.743,1.368 -1.743,1.368 -1.657,1.282 -1.652,1.274 -1.65,1.265 -1.65,1.265 -1.65,1.15 -1.653,1.137 -1.663,1.128 -1.675,1.125 -1.675,1.125
  Top Layer pour cut-out: -2.2,2.2 -2.2,-2.2 2.2,-2.2 2.2,2.2
  silkscreen extent -2,-2 2,2, body extent -2,-2 2,2, height 0.81
QFN48_M040_6.0X6.0_EP4.3X4.3_SL_EFR32MG24 [mm] "QFN48, Pitch 0.4, 6.0x6.0 H0.9 (210603)"
  rrect5% 4.45x4.45 smd paste-100: 0(0,0)
  rrect100% 0.86x0.22 smd: 1(-2.935,2.2) 2(-2.935,1.8) 3(-2.935,1.4) 4(-2.935,1) 5(-2.935,0.6) 6(-2.935,0.2) 7(-2.935,-0.2) 8(-2.935,-0.6) 9(-2.935,-1) 10(-2.935,-1.4) 11(-2.935,-1.8) 12(-2.935,-2.2) 25(2.935,-2.2) 26(2.935,-1.8) 27(2.935,-1.4) 28(2.935,-1) 29(2.935,-0.6) 30(2.935,-0.2) 31(2.935,0.2) 32(2.935,0.6) 33(2.935,1) 34(2.935,1.4) 35(2.935,1.8) 36(2.935,2.2)
  rrect100% 0.22x0.86 smd: 13(-2.2,-2.935) 14(-1.8,-2.935) 15(-1.4,-2.935) 16(-1,-2.935) 17(-0.6,-2.935) 18(-0.2,-2.935) 19(0.2,-2.935) 20(0.6,-2.935) 21(1,-2.935) 22(1.4,-2.935) 23(1.8,-2.935) 24(2.2,-2.935) 37(2.2,2.935) 38(1.8,2.935) 39(1.4,2.935) 40(1,2.935) 41(0.6,2.935) 42(0.2,2.935) 43(-0.2,2.935) 44(-0.6,2.935) 45(-1,2.935) 46(-1.4,2.935) 47(-1.8,2.935) 48(-2.2,2.935)
  silkscreen extent -3,-3 3,3, body extent -3.05,-3.05 3.05,3.05, height 0.91
R0201_L [mm] "Resistor (Chip2PinSM127P600-8N)"
  rrect25% 0.34x0.32 smd: 1(-0.3,0) 2(0.3,0)
  silkscreen extent -0.29,-0.15 0.29,0.15, body extent -0.32,-0.13 0.32,0.13, height 0.3
R0402_L [mm] "Chip Resistor, 2-Leads, Body 1.0x0.5mm, IPC High Density (170210)"
  rrect20% 0.6x0.6 smd mask+0.051: 1(-0.45,0) 2(0.45,0)
  silkscreen extent -0.5,-0.25 0.5,0.25, body extent -0.5,-0.25 0.5,0.25, height 0.6
SENS_VISH_VEML6035 [mm] "(200529)"
  rrect25% 0.65x0.5 smd: 1(-0.825,0.65) 2(-0.825,0) 3(-0.825,-0.65) 4(0.825,-0.65) 5(0.825,0) 6(0.825,0.65)
  silkscreen extent -1,-1 1,1, body extent -1,-1 1,1, height 0.41
SOT23-5_L [mm] "SOT23, 5-Leads, Body 2.95x2.80mm, Pitch 0.95mm, IPC High Dens (170221)"
  rrect50% 0.9x0.6 smd: 1(-1.2,0.95) 2(-1.2,0) 3(-1.2,-0.95) 4(1.2,-0.95) 5(1.2,0.95)
  silkscreen extent -1.33,-1.55 1.3,1.55, body extent -0.87,-1.55 0.87,1.55, height 1.46
SOT23_123_L [mm] "SOT23, 3-Leads, Body 2.95x2.80mm, Pitch 0.95mm, HiDens (171129)"
  rrect50% 0.9x0.6 smd: 1(-1.2,0.95) 2(-1.2,-0.95) 3(1.2,0)
  silkscreen extent -1.33,-1.55 1.3,1.55, body extent -1.32,-1.5 1.32,1.5, height 1.08
SOT553_L [mm] "SOT553 (_M050_W1.2_), 5-Leads, Body 1.60x1.20mm, Pitch 0.5mm, IPC High Density"
  rrect25% 0.6x0.3 smd: 1(-0.65,0.5) 2(-0.65,0) 3(-0.65,-0.5) 4(0.65,-0.5) 5(0.65,0.5)
  silkscreen extent -0.65,-0.85 0.65,0.85, body extent -0.65,-0.85 0.65,0.85, height 0.6
SOT563_L [mm] "SOT563 (_M050_W1.2_), 6-Leads, Body 1.60x1.20mm, Pitch 0.5mm, IPC High Density"
  rrect25% 0.6x0.3 smd: 1(-0.65,0.5) 2(-0.65,0) 3(-0.65,-0.5) 4(0.65,-0.5) 5(0.65,0) 6(0.65,0.5)
  silkscreen extent -0.65,-0.85 0.65,0.85, body extent -0.65,-0.85 0.65,0.85, height 0.6
SOT663_NXP [mm] "(201120)"
  rrect25% 0.55x0.55 smd paste-0.025: 1(-0.825,0.5) 2(-0.825,-0.5) 3(0.825,0)
  silkscreen extent -0.65,-0.85 0.65,0.85, body extent -0.65,-0.85 0.65,0.85, height 0.6
SW_CK_PTS810 [mm] "Switch, C&K, PTS810"
  rrect20% 1.05x0.65 smd: 1(-2.075,1.075) 2(2.075,1.075) 3(-2.075,-1.075) 4(2.075,-1.075)
  silkscreen extent -2.3,-1.6 2.3,1.6, body extent -2.1,-1.63 2.1,1.63, height 2.6
TDFN8_M050_2.0X3.0_EP [mm] "TDFN8_M050_2.0x3.0_EP"
  rrect25% 0.75x0.3 smd: 1(-1.5,0.75) 2(-1.5,0.25) 3(-1.5,-0.25) 4(-1.5,-0.75) 5(1.5,-0.75) 6(1.5,-0.25) 7(1.5,0.25) 8(1.5,0.75)
  rrect1% 1.36x1.46 smd paste-0.07: 9(0,0)
  silkscreen extent -1.5,-1 1.5,1, body extent -1.5,-1 1.5,1, height 1.01
TESTJIGG_PCB4166_MECH2_SL [mm]
  round 1 on Mech2: 7(-14.41,-7.3) 7(-11.75,-0.35) 7(-11.596,24.385) 7(-9.6,0.67) 7(-2.2,8.35) 7(-2.2,10.95) 7(-2.15,15.65) 7(-1.26,13.28) 7(-0.05,2.55) 7(0,0) 7(0.35,16.13) 7(1.27,10.8) 7(1.27,13.32) 7(6.095,24.385) 7(6.5,0) 7(6.85,4.45) 7(7.7,8.5) 7(8.2,16.7) 7(8.6,11.45) 7(8.6,14.05) 7(8.85,6) 7(10.1,3.75)
  rect 6.7x6.7 on Mech2: 9(-6.8,7.3)
  Bottom Layer keep-out region: 6.095,24.885 6.345,24.818 6.528,24.635 6.595,24.385 6.595,24.385 6.528,24.135 6.345,23.952 6.095,23.885 6.095,23.885 5.845,23.952 5.662,24.135 5.595,24.385 5.595,24.385 5.662,24.635 5.845,24.818 6.095,24.885
  Bottom Layer keep-out region: 6.095,24.885 6.345,24.818 6.528,24.635 6.595,24.385 6.595,24.385 6.528,24.135 6.345,23.952 6.095,23.885 6.095,23.885 5.845,23.952 5.662,24.135 5.595,24.385 5.595,24.385 5.662,24.635 5.845,24.818 6.095,24.885
  Bottom Layer keep-out region: 0.35,16.63 0.6,16.563 0.783,16.38 0.85,16.13 0.85,16.13 0.783,15.88 0.6,15.697 0.35,15.63 0.35,15.63 0.1,15.697 -0.083,15.88 -0.15,16.13 -0.15,16.13 -0.083,16.38 0.1,16.563 0.35,16.63
  Bottom Layer keep-out region: -2.15,16.15 -1.9,16.083 -1.717,15.9 -1.65,15.65 -1.65,15.65 -1.717,15.4 -1.9,15.217 -2.15,15.15 -2.15,15.15 -2.4,15.217 -2.583,15.4 -2.65,15.65 -2.65,15.65 -2.583,15.9 -2.4,16.083 -2.15,16.15
  Bottom Layer keep-out region: 1.27,13.82 1.52,13.753 1.703,13.57 1.77,13.32 1.77,13.32 1.703,13.07 1.52,12.887 1.27,12.82 1.27,12.82 1.02,12.887 0.837,13.07 0.77,13.32 0.77,13.32 0.837,13.57 1.02,13.753 1.27,13.82
  Bottom Layer keep-out region: -1.26,13.78 -1.01,13.713 -0.827,13.53 -0.76,13.28 -0.76,13.28 -0.827,13.03 -1.01,12.847 -1.26,12.78 -1.26,12.78 -1.51,12.847 -1.693,13.03 -1.76,13.28 -1.76,13.28 -1.693,13.53 -1.51,13.713 -1.26,13.78
  Bottom Layer keep-out region: 1.27,11.3 1.52,11.233 1.703,11.05 1.77,10.8 1.77,10.8 1.703,10.55 1.52,10.367 1.27,10.3 1.27,10.3 1.02,10.367 0.837,10.55 0.77,10.8 0.77,10.8 0.837,11.05 1.02,11.233 1.27,11.3
  Bottom Layer keep-out region: -2.2,11.45 -1.95,11.383 -1.767,11.2 -1.7,10.95 -1.7,10.95 -1.767,10.7 -1.95,10.517 -2.2,10.45 -2.2,10.45 -2.45,10.517 -2.633,10.7 -2.7,10.95 -2.7,10.95 -2.633,11.2 -2.45,11.383 -2.2,11.45
  Bottom Layer keep-out region: -2.2,8.85 -1.95,8.783 -1.767,8.6 -1.7,8.35 -1.7,8.35 -1.767,8.1 -1.95,7.917 -2.2,7.85 -2.2,7.85 -2.45,7.917 -2.633,8.1 -2.7,8.35 -2.7,8.35 -2.633,8.6 -2.45,8.783 -2.2,8.85
  Bottom Layer keep-out region: 8.2,17.2 8.45,17.133 8.633,16.95 8.7,16.7 8.7,16.7 8.633,16.45 8.45,16.267 8.2,16.2 8.2,16.2 7.95,16.267 7.767,16.45 7.7,16.7 7.7,16.7 7.767,16.95 7.95,17.133 8.2,17.2
  Bottom Layer keep-out region: 8.6,14.55 8.85,14.483 9.033,14.3 9.1,14.05 9.1,14.05 9.033,13.8 8.85,13.617 8.6,13.55 8.6,13.55 8.35,13.617 8.167,13.8 8.1,14.05 8.1,14.05 8.167,14.3 8.35,14.483 8.6,14.55
  Bottom Layer keep-out region: 8.6,11.95 8.85,11.883 9.033,11.7 9.1,11.45 9.1,11.45 9.033,11.2 8.85,11.017 8.6,10.95 8.6,10.95 8.35,11.017 8.167,11.2 8.1,11.45 8.1,11.45 8.167,11.7 8.35,11.883 8.6,11.95
  Bottom Layer keep-out region: 7.7,9 7.95,8.933 8.133,8.75 8.2,8.5 8.2,8.5 8.133,8.25 7.95,8.067 7.7,8 7.7,8 7.45,8.067 7.267,8.25 7.2,8.5 7.2,8.5 7.267,8.75 7.45,8.933 7.7,9
  Bottom Layer keep-out region: 8.85,6.5 9.1,6.433 9.283,6.25 9.35,6 9.35,6 9.283,5.75 9.1,5.567 8.85,5.5 8.85,5.5 8.6,5.567 8.417,5.75 8.35,6 8.35,6 8.417,6.25 8.6,6.433 8.85,6.5
  Bottom Layer keep-out region: 10.1,4.25 10.35,4.183 10.533,4 10.6,3.75 10.6,3.75 10.533,3.5 10.35,3.317 10.1,3.25 10.1,3.25 9.85,3.317 9.667,3.5 9.6,3.75 9.6,3.75 9.667,4 9.85,4.183 10.1,4.25
  Bottom Layer keep-out region: 6.85,4.95 7.1,4.883 7.283,4.7 7.35,4.45 7.35,4.45 7.283,4.2 7.1,4.017 6.85,3.95 6.85,3.95 6.6,4.017 6.417,4.2 6.35,4.45 6.35,4.45 6.417,4.7 6.6,4.883 6.85,4.95
  Bottom Layer keep-out region: 6.5,0.5 6.75,0.433 6.933,0.25 7,0 7,0 6.933,-0.25 6.75,-0.433 6.5,-0.5 6.5,-0.5 6.25,-0.433 6.067,-0.25 6,0 6,0 6.067,0.25 6.25,0.433 6.5,0.5
  Bottom Layer keep-out region: -0.05,3.05 0.2,2.983 0.383,2.8 0.45,2.55 0.45,2.55 0.383,2.3 0.2,2.117 -0.05,2.05 -0.05,2.05 -0.3,2.117 -0.483,2.3 -0.55,2.55 -0.55,2.55 -0.483,2.8 -0.3,2.983 -0.05,3.05
  Bottom Layer keep-out region: 0,0.5 0.25,0.433 0.433,0.25 0.5,0 0.5,0 0.433,-0.25 0.25,-0.433 0,-0.5 0,-0.5 -0.25,-0.433 -0.433,-0.25 -0.5,0 -0.5,0 -0.433,0.25 -0.25,0.433 0,0.5
  Bottom Layer keep-out region: -9.6,1.17 -9.35,1.103 -9.167,0.92 -9.1,0.67 -9.1,0.67 -9.167,0.42 -9.35,0.237 -9.6,0.17 -9.6,0.17 -9.85,0.237 -10.033,0.42 -10.1,0.67 -10.1,0.67 -10.033,0.92 -9.85,1.103 -9.6,1.17
  Bottom Layer keep-out region: -11.75,0.15 -11.5,0.083 -11.317,-0.1 -11.25,-0.35 -11.25,-0.35 -11.317,-0.6 -11.5,-0.783 -11.75,-0.85 -11.75,-0.85 -12,-0.783 -12.183,-0.6 -12.25,-0.35 -12.25,-0.35 -12.183,-0.1 -12,0.083 -11.75,0.15
  Bottom Layer keep-out region: -14.41,-6.8 -14.16,-6.867 -13.977,-7.05 -13.91,-7.3 -13.91,-7.3 -13.977,-7.55 -14.16,-7.733 -14.41,-7.8 -14.41,-7.8 -14.66,-7.733 -14.843,-7.55 -14.91,-7.3 -14.91,-7.3 -14.843,-7.05 -14.66,-6.867 -14.41,-6.8
TP_1.0_SMD [mm] "Test Point, 1.0 mm, SMD (170306)"
  round 1 smd paste-0.501: 1(0,0)
  silkscreen extent -0.5,-0.5 0.5,0.5
WCON_WF1001A-WM04E-4 [mm] "WCON, WF1001A-WM04ER1 4-terminal H: 4.87 (200622)"
  rrect25% 0.6x1.55 smd: 1(-1.5,-2.975) 2(-0.5,-2.975) 3(0.5,-2.975) 4(1.5,-2.975)
  rrect25% 1.2x1.8 smd: 5(-2.8,0) 6(2.8,0)
  silkscreen extent -3.15,-2.76 3.15,0.63, body extent -3.15,-2.2 3.15,0.7, height 4.91
WLCSP12_M035X040_1.99X2.23_MXIC [mm] "WL-CSP, 12 Leads, Body 1.99x2.23 H:0.5, Pitch 0.35 x 0.40 (170314)"
  round 0.2 smd mask+0.04: A1(-0.7,0.6) A5(0.7,0.6) B2(-0.35,0.4) B4(0.35,0.4) C3(0,0.2) D2(-0.35,0) D4(0.35,0) E3(0,-0.2) F2(-0.35,-0.4) F4(0.35,-0.4) G1(-0.7,-0.6) G5(0.7,-0.6)
  silkscreen extent -0.99,-1.11 0.99,1.11, body extent -1,-1.12 1,1.12, height 0.52
X_KDS_DST1610A_1610 [mm] "Crystal KDS DST1610A (2 pin) (190827)"
  rrect25% 0.4x0.8 smd mask+0.051: 1(-0.5,0) 2(0.5,0)
  silkscreen extent -0.8,-0.5 0.8,0.5, body extent -0.8,-0.5 0.8,0.5, height 0.45
X_KDS_DSX211SH_2.0X1.65-4 [mm] "X_KDS_DSX211SH_2.0X1.65-4"
  rrect20% 0.9x0.8 smd: 1(-0.7,-0.55) 2(0.7,-0.55) 3(0.7,0.55) 4(-0.7,0.55)
  silkscreen extent -1.02,-0.82 1.02,0.82, body extent -1.07,-0.87 1.07,0.87, height 0.5
X_SSS_DSX211SH_2.05X1.65-4 [mm] "X_SSS_DSX211SH_2.05X1.65-4"
  rrect20% 0.9x0.8 smd mask+0.051: 1(-0.7,-0.55) 2(0.7,-0.55) 3(0.7,0.55) 4(-0.7,0.55)
  silkscreen extent -1.02,-0.82 1.02,0.82, body extent -1.07,-0.87 1.07,0.87, height 0.51

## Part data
LED900: library part Blue

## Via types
v1: diameter 0.5, hole 0.25, Top Layer to Bottom Layer, tented both sides, 478 vias

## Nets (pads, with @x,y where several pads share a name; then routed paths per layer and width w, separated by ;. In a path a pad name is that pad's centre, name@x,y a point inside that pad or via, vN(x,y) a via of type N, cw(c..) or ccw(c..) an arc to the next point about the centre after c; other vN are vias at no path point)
3V3: C917.1 EXP1.20 Q901.1 Q902.4 R908.2 R918.2 U902.1 U902.4 | length 71.5
  Signal Layer 5 w0.6: v1(7.25,46) v1(7.95,46) 8.2,45.75 8.2,43.2 v1(8.8,42.6) v1(8.8,41.9) 7.55,40.65 7.3,40.65 6.65,40 6.6,40 6.6,39.4 7.325,38.675 8.025,38.675 8.9,37.8 8.9,32.2 9,32.1 9,30.593 9.2,30.393 9.2,29.2 7.1,27.1 7.1,20.9 14.7,13.3 23.9,13.3 24.7,12.5 EXP1.20@27.886,12.5
  Signal Layer 6 w0.7: v1(3.9,43.425) 2.675,44.65 2.675,45.25 3.125,45.7 4.15,45.7 v1(4.425,45.975) v1(5.075,45.975) 7.925,45.975 v1(7.95,46)
  Bottom Layer w0.1: R908.2@4.775,48.3 4.775,48.29 R908.2@4.884,48.181 ; U902.4@5.601,46.799 5.675,46.725 U902.4@5.675,46.6
  Bottom Layer w0.2: R908.2@4.775,48.29 4.775,47.075 5.25,46.6 5.475,46.6
  Bottom Layer w0.3: v1@3.9,43.675 4.05,43.825 R918.2@4.5,43.825
  Bottom Layer w0.381: v1@4.85,45.975 v1@4.874,45.999 ; U902.1@7.175,46.6 7.175,46.075 v1(7.25,46)
  Bottom Layer w0.4: Q901.1@8.3,41.363 8.563,41.363 8.8,41.6 v1(8.8,41.9) v1(8.8,42.6)
  Bottom Layer w0.508: v1@4.275,45.8 4.45,45.975 v1@4.85,45.975 ; v1@4.874,45.999 5.475,46.6 U902.4@5.629,46.6
  Bottom Layer w0.635: v1@3.9,43.675 v1(3.9,43.425) 3.9,43.175 4.1,42.975 Q902.4@4.431,42.975 ; v1@7.285,46.075 7.36,46 v1(7.95,46) 7.95,46.075 C917.1@8.475,46.6
5V: C915.1 C916.1 D901.1 EXP1.18 Q901.2 Q901.5 R907.2 R915.2 U902.2 | length 70.6
  Signal Layer 5 w0.203: v1@7.273,45.15 6.7,45.723 6.7,48.325 v1(8.025,49.65)
  Signal Layer 5 w0.6: v1(5.3,38.85) 4.775,38.85 ; v1(7.5,45.15) 7.075,45.15 4.775,42.85 4.775,38.85 ; v1(8.85,16.875) 8.85,17.4 4.4,21.85 4.15,21.85 3.8,22.2 3.8,22.85 4.45,23.5 4.45,27.1 3.703,27.847 3.703,37.097 3.325,37.475 3.325,38.15 4.025,38.85 4.775,38.85
  Signal Layer 6 w0.635: v1(8.85,16.875) 9.35,17.375 10.475,17.375 11.675,16.175 26.751,16.175 EXP1.18@27.886,15.04
  Bottom Layer w0.1: v1(5.3,38.85) 7.15,40.7 7.55,40.7 7.65,40.8 Q901.2@7.65,41.363 Q901.5@7.65,43.188
  Bottom Layer w0.203: R907.2@7.5,49.65 v1@8,49.65
  Bottom Layer w0.381: C915.1@6.396,45.096 6.675,45.375 C916.1@6.675,45.85 U902.2@6.675,46.6
  Bottom Layer w0.635: C915.1@6.475,45.15 v1(7.5,45.15) ; v1(8.85,16.875) 8.85,18.5 D901.1@8.85,19.075
ADC_VREF: C117.1 R116.1 U1.27 | length 9.6
  Top Layer w0.1: C117.1@6.2,38 C117.1@6.4,38.2 ; v1(6.225,38.85) 6.325,38.75 6.325,38.375 6.45,38.25 C117.1@6.4,38.2 ; U1.27@8.565,38.2 C117.1@6.4,38.2
  Top Layer w0.2: v1(3.3,41.825) 3.925,42.45 R116.1@4.7,42.45
  Signal Layer 6 w0.2: v1(3.3,41.825) 3.3,40.925 4.075,40.15 5.025,40.15 6.225,38.95 v1(6.225,38.85)
ADC_VREF_ENABLE: U1.28 U101.12 | length 16.3
  Top Layer w0.1: v1(7.75,37.8) U1.28@8.565,37.8
  Signal Layer 4 w0.1: v1(7.75,37.8) 8.2,38.25 13.975,38.25 15.425,39.7 18.605,39.7 v1(20.99,42.085)
  Bottom Layer w0.1: U101.12@20.5,42.085 v1(20.99,42.085)
BOARD_ID_SCL: EXP1.17 R911.1 TPJ14.1 U900.H13 U903.6 | length 56.1
  Signal Layer 4 w0.102: EXP1.17@2.486,15.04 4.796,17.35 9.125,17.35 v1(9.825,16.65) 10.425,16.05 17.8,16.05 19.5,17.75 21.025,17.75 23.3,15.475 24.5,15.475 26.025,13.95 v1(27.125,13.95)
  Signal Layer 5 w0.102: v1(25.9,29.7) 26.725,28.875 26.725,14.35 v1(27.125,13.95)
  Bottom Layer w0.102: U900.H13@9.75,22.5 9.975,22.275 9.975,20.992 9.974,20.659 9.975,20.625 10.75,19.85 10.75,17.425 9.975,16.65 v1(9.825,16.65) ; U903.6@21.575,29.975 R911.1@22.475,29.975 ; R911.1@22.475,30 R911.1@22.5,29.975 22.825,30.3 23.975,30.3 ; 23.975,30.275 TPJ14.1@24.55,29.7 v1(25.9,29.7)
BOARD_ID_SDA: EXP1.19 R910.1 TPJ15.1 U900.G13 U900.H12 U900.J12 U903.5 | length 51.3
  Signal Layer 4 w0.1: EXP1.19@2.486,12.5 4.45,12.5 8.125,16.175 v1(8.55,16.175) 9.35,15.375 17.975,15.375 v1(19.8,17.2)
  Signal Layer 5 w0.1: v1(19.275,31) 19.275,29.375 18.775,28.875 18.775,28.125 19.425,27.475 19.425,21.25 18.75,20.575 18.75,19.675 19.2,19.225 19.2,17.8 v1(19.8,17.2)
  Bottom Layer w0.1: v1(8.55,16.175) 9.1,16.175 9.337,16.412 9.337,16.837 9.638,17.138 10.063,17.138 10.4,17.475 10.4,19.875 9.75,20.525 9.75,22 U900.G13@9.25,22.5 U900.H12@9.75,23 U900.J12@10.25,23 ; v1(19.275,31) 19.275,30.975 19.6,30.65 20.9,30.65 21.075,30.475 U903.5@21.575,30.475 21.65,30.55 22.425,30.55 R910.1@22.5,30.625 22.825,30.95 22.825,32.125 23.05,32.35 24.5,32.35 TPJ15.1@24.55,32.3
BOARD_ID_WP: R912.1 TPJ16.1 U900.F13 U903.7 | length 27.9
  Signal Layer 4 w0.102: v1(9,22.1) 10.175,22.1 12.3,19.975 13.075,19.975 13.875,19.175 17.1,19.175 17.575,19.65 19.9,19.65 v1(20.475,19.075)
  Bottom Layer w0.102: U900.F13@8.75,22.5 9,22.25 v1(9,22.1) ; TPJ16.1@22.45,18.25 21.3,18.25 v1(20.475,19.075) 20.95,19.55 20.95,29.125 21.3,29.475 U903.7@21.575,29.475 22.425,29.475 R912.1@22.5,29.4
BUTTON0: C142.1 EXP1.3 R140.2 SW100.1 SW100.2 U1.19 U900.A6 | length 78.2
  Top Layer w0.1: v1(10.95,40.55) 11.3,40.2 U1.19@11.3,39.735 ; v1(22.2,1.525) 22.2,3.05 R140.2@22.75,3.6 ; R140.2@22.75,3.5 R140.2@22.825,3.425 ; R140.2@22.825,3.525 23.975,3.525 SW100.1@24.225,3.275 SW100.2@28.375,3.275
  Signal Layer 4 w0.1: EXP1.3@2.486,32.82 1.375,31.709 1.375,24.675 v1(1.975,24.075) 1.3,23.4 1.3,4.775 2.525,3.55 18.55,3.55 20.575,1.525 v1(22.2,1.525)
  Bottom Layer w0.1: v1(1.975,24.075) 3.025,24.075 4.15,25.2 5.025,25.2 5.6,25.775 6.025,25.775 U900.A6@6.25,26 ; EXP1.3@2.486,32.82 3.845,32.82 6.475,35.45 6.475,35.925 6.75,36.2 7.35,36.2 8.625,37.475 8.625,39.05 9.15,39.575 9.975,39.575 v1(10.95,40.55)
BUTTON1: C145.1 EXP1.11 R143.2 SW101.1 SW101.2 U1.18 U900.A5 | length 55.6
  Top Layer w0.1: SW101.1@2.025,3.275 2.25,3.5 v1(2.25,4.625) ; SW101.1@2.175,3.275 2.4,3.5 5.75,3.5 5.975,3.275 SW101.2@6.175,3.275 6.45,3.55 C145.1@7.1,3.55 ; C145.1@7.1,3.45 7.6,3.45 R143.2@7.65,3.5 ; v1(11.625,40.55) 11.7,40.475 U1.18@11.7,39.735
  Signal Layer 4 w0.1: v1(2.25,4.625) 1.525,5.35 1.525,21.699 EXP1.11@2.486,22.66
  Bottom Layer w0.1: EXP1.11@2.486,22.66 1.475,23.671 1.475,25.675 2.1,26.3 ; U900.A5@6.25,26.5 6.05,26.5 5.525,25.975 4,25.975 3.875,25.85 3.225,25.85 2.775,26.3 2.1,26.3 ; v1(11.625,40.55) 10.35,39.275 9.35,39.275 9,38.925 9,37.25 3.625,31.875 3.625,29.525 2.925,28.825 2,28.825 1.45,28.275 1.45,26.95 2.1,26.3
CTRL_MCU_PA0: R919.1 U900.C2 U900.D3 | length 2.7
  Bottom Layer w0.1: R919.1@6.4,29.6 7,29 7,28.25 U900.C2@7.25,28 U900.D3@7.75,27.5
CTRL_MCU_PA1: R920.1 U900.C1 | length 1.1
  Bottom Layer w0.1: U900.C1@7.25,28.5 R920.1@7.25,29.575
CTRL_MCU_PB9: TPJ17.1 U900.L8 U900.M7 | length 6.2
  Signal Layer 6 w0.1: v1(10.15,25) 11.325,25 v1@12.8,26.475
  Bottom Layer w0.1: v1(10.15,25) U900.L8@11.25,25 U900.M7@11.75,25.5 ; v1(12.725,26.475) 12.725,26.516 13.666,26.516 TPJ17.1@13.75,26.6
CTRL_MCU_PB10: R905.1 U900.L9 | length 31.8
  Top Layer w0.2: R905.1@18.725,6.1 19.125,6.5 19.125,8.725 19.9,9.5 21.75,9.5 22.5,10.25 v1(22.5,15.175)
  Signal Layer 5 w0.1: 9.1,24.05 9.124,24.05 9.624,24.55 v1(9.7,24.55)
  Signal Layer 5 w0.2: 9.1,24.05 9.094,24.044 9.094,23.281 12.461,19.914 13.161,19.914 17.9,15.175 v1(22.5,15.175)
  Bottom Layer w0.1: v1(9.7,24.55) 9.75,24.5 10.325,24.5 10.558,24.733 11.017,24.733 U900.L9@11.25,24.5
CTRL_MCU_PB13: U900.N9 X900.3 | length 3.2
  Bottom Layer w0.1: U900.N9@12.25,24.5 13.425,24.5 13.6,24.675 14.525,24.675 X900.3@15.15,25.3
CTRL_MCU_PB14: U900.N10 X900.1 | length 2.1
  Bottom Layer w0.1: U900.N10@12.25,24 12.525,24.275 13.675,24.275 X900.1@14.05,23.9
CTRL_MCU_PC2: R921.1 U900.L1 | length 0.9
  Bottom Layer w0.1: U900.L1@11.25,28.5 R921.1@11.25,29.427
CTRL_MCU_PC12: U900.D11 U900.D12 | length 0.5
  Bottom Layer w0.1: U900.D12@7.75,23 U900.D11@7.75,23.5
CTRL_MCU_PC14: U900.C12 U900.C13 | length 0.5
  Bottom Layer w0.1: U900.C13@7.25,22.5 U900.C12@7.25,23
CTRL_MCU_PD0: C923.1 R901.1 U900.L10 | length 5.3
  Top Layer w0.1: v1@10.742,24.326 v1@10.749,24.326
  Signal Layer 5 w0.1: v1@10.742,24.326 12.1,22.968 v1@12.1,21.35
  Bottom Layer w0.1: v1@10.742,24.326 10.742,24.308 11.05,24 U900.L10@11.25,24 ; C923.1@11.425,20.85 12,20.85 12.05,20.9 v1(12.05,21.4)
  other v1: 10.767,24.326
CTRL_MCU_PD5: R930.1 U900.N13 | length 1.1
  Bottom Layer w0.1: U900.N13@12.25,22.5 12.25,21.95 R930.1@12.625,21.575
CTRL_MCU_PE0: TPJ11.1 U900.G11 | length 20.8
  Signal Layer 4 w0.1: v1(9.025,24.526) 9.025,23.8 9.325,23.5 17.5,23.5 17.8,23.2 19.375,23.2 19.925,23.75 25.7,23.75 v1(26.025,24.075)
  Bottom Layer w0.1: v1(9.025,24.526) 9.025,23.725 U900.G11@9.25,23.5 U900.G11@9.206,23.5 ; TPJ11.1@24.8,24.25 24.875,24.175 25.925,24.175 v1(26.025,24.075)
CTRL_MCU_PE4: R931.1 U900.C11 | length 13.1
  Signal Layer 5 w0.2: v1(9.525,25.201) 9.949,25.625 11.544,25.625 11.794,25.875 15.8,25.875 v1(17.2,27.275)
  Bottom Layer w0.1: U900.C11@7.25,23.5 7.555,23.805 8.23,23.805 8.6,24.175 8.6,24.675 8.9,24.975 9.299,24.975 v1(9.525,25.201)
  Bottom Layer w0.3: R931.1@16.5,28.1 16.5,27.6 16.825,27.275 v1(17.2,27.275)
CTRL_MCU_PE14: TPJ5.1 U900.A2 | length 12.6
  Signal Layer 6 w0.1: v1(5.66,28.081) 5.898,28.32 11.745,28.32 12.35,28.925 13.925,28.925 v1(15.075,30.075)
  Bottom Layer w0.1: v1(5.66,28.081) 5.741,28 U900.A2@6.25,28
  Bottom Layer w0.102: TPJ5.1@13.75,29.2 14.625,30.075 v1(15.075,30.075)
CTRL_MCU_PE15: TPJ6.1 U900.A1 | length 13.5
  Signal Layer 6 w0.1: v1(5.66,28.725) 11.5,28.725 12.15,29.375 13.65,29.375 15.198,30.923 v1(16.566,30.923)
  Bottom Layer w0.1: v1@5.55,28.725 v1(5.66,28.725) 6.025,28.725 U900.A1@6.25,28.5
  Bottom Layer w0.102: v1(16.566,30.923) 16.573,30.923 TPJ6.1@17.22,31.57
CTRL_MCU_PF0: TPJ2.1 U900.C10 | length 17.5
  Signal Layer 5 w0.1: v1(8.895,25.381) 10.113,26.6 11.775,26.6 12.25,27.075 14.55,27.075 15.85,28.375 15.85,30.825 17.025,32 v1(17.025,33.3)
  Bottom Layer w0.1: U900.C10@7.25,24 7.467,24 7.472,24.005 8.03,24.005 8.35,24.325 8.35,24.725 8.895,25.27 v1(8.895,25.381) ; TPJ2.1@16.3,34.38 17.025,33.655 v1(17.025,33.3)
CTRL_MCU_PF1: TPJ1.1 U900.A9 U900.B10 | length 16.9
  Signal Layer 4 w0.1: v1(5.823,24.566) 7.189,23.2 14.3,23.2 16.925,20.575 v1(16.925,20.2)
  Bottom Layer w0.1: v1@5.741,24.666 v1@5.907,24.5 ; v1(5.823,24.566) 5.889,24.5 v1@5.907,24.5 ; U900.B10@6.75,24 U900.A9@6.25,24.5 v1@5.907,24.5 ; TPJ1.1@15.95,18.25 16.925,19.225 v1(16.925,20.2)
CTRL_MCU_PF2: TPJ3.1 U900.A10 | length 16.9
  Signal Layer 4 w0.1: v1(5.823,23.926) 6.849,22.9 14.1,22.9 16.425,20.575 16.425,20 16.7,19.725 17.1,19.725 17.65,20.275 v1(17.65,20.8)
  Bottom Layer w0.1: v1(5.823,23.926) 5.896,24 U900.A10@6.25,24 ; TPJ3.1@15.9,20.8 v1(17.65,20.8)
CTRL_MCU_PF5: TP999.1 U900.A8 | length 29.6
  Signal Layer 5 w0.1: TP999.1@4.65,2.5 2.775,4.375 2.775,7.25 3.505,7.98 3.505,10.846 3.959,11.3 6.25,11.3 9.4,14.45 9.4,17.7 6.5,20.6 6.5,24.533 v1(5.823,25.21)
  Bottom Layer w0.1: v1@5.832,25.219 6.051,25 U900.A8@6.25,25
CTRL_MCU_PF10: R903.2 U900.B13 | length 1.5
  Bottom Layer w0.2: U900.B13@6.75,22.5 6.63,22.38 6.63,21.32 R903.2@6.8,21.15
CTRL_MCU_PF11: R904.2 U900.A13 | length 1.5
  Bottom Layer w0.2: R904.2@5.925,21.15 6.325,21.55 6.325,22.425 U900.A13@6.25,22.5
